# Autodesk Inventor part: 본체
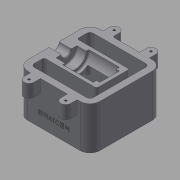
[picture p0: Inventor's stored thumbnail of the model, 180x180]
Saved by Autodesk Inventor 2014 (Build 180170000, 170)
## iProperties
Created: 2018-01
Part Number: 본체
Material: Generic
Document SubType Name: Modeling
Designer: user
Density: 1 g/cm^3
Appearance: Default
Author: user
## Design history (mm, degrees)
sketch "스케치2"
  geometry: L1 (-55, -55)-(55, -55); L2 (55, -55)-(55, 55); L3 (55, 55)-(-55, 55); L4 (-55, 55)-(-55, -55); L5 (-55, -55)-(55, 55); L6 (55, -55)-(-55, 55); 3 further points
  constraints: 12 end point, 3 midpoint, 2 parallel, 1 coincident, 1 horizontal, 1 perpendicular
  dimensions: "d2" = 110 distance of L2.end L3.end; "d3" = 110 distance of L1.end L2.end
extrude "돌출1" new body sketch "스케치2" stored distance "d4" = 65; taper "d5" = 0 deg
fillet "모깎기1" dims "d6" = 15
sketch "스케치3"
  geometry: L1 (40, 55)-(-40, 55) reference; L2 (-55, 40)-(-55, -40) reference; L3 (-40, -55)-(40, -55) reference; L4 (55, -40)-(55, 40) reference; L5 (-40, 45)-(40, 45); L6 (45, 40)-(45, -40); L7 (40, -45)-(-40, -45); L8 (-45, 25)-(-45, 40); L9 (0, 25)-(0, -25); L10 (-45, -25)-(-45, -40); L11 (-45, 25)-(32, 25); L12 (35, 22)-(35, -22); L13 (-45, -25)-(32, -25); A1 r 15 centre (40, 40) between (55, 40) and (40, 55) reference; A2 r 15 centre (-40, 40) between (-40, 55) and (-55, 40) reference; A3 r 15 centre (-40, -40) between (-55, -40) and (-40, -55) reference; A4 r 15 centre (40, -40) between (40, -55) and (55, -40) reference; A5 r 5 centre (40, 40) between (45, 40) and (40, 45); A6 r 5 centre (40, -40) between (40, -45) and (45, -40); A7 r 5 centre (-40, -40) between (-45, -40) and (-40, -45); A8 r 5 centre (-40, 40) between (-40, 45) and (-45, 40); A9 r 3 centre (32, 22) between (35, 22) and (32, 25); A10 r 3 centre (32, -22) between (32, -25) and (35, -22); 2 further points
  constraints: 18 end point, 12 point on circle, 6 centre point, 5 tangent, 3 perpendicular, 2 point on line, 1 coincident, 1 equal radius, 1 horizontal alignment, 1 midpoint, 1 parallel, 7 other
  dimensions: "d7" = 10 distance between parallel lines of L1 L5; "d8" = 50 distance of L9.start L9.end; "d66" = 20 distance between parallel lines of L12 L4; "d67" = 3 radius of A9
extrude "돌출2" cut sketch "스케치3" stored distance "d13" = 95.3375; taper "d14" = 0 deg
sketch "스케치4"
  geometry: L1 (-55, 32.5)-(-40, 32.5) reference; L2 (-55, 32.5)-(30, 32.5); L3 (30, 32.5)-(30, 46.5); L4 (29, 47.5)-(25, 47.5); L5 (25, 47.5)-(25, 51.5); L6 (24, 52.5)-(-21, 52.5); L7 (-22, 51.5)-(-22, 48.5); L8 (-22, 48.5)-(-35, 48.5); L9 (-36, 47.5)-(-36, 40); L10 (-36, 40)-(-55, 40); L11 (-55, 40)-(-55, 32.5); A1 r 1 centre (-35, 47.5) between (-35, 48.5) and (-36, 47.5); A2 r 1 centre (-21, 51.5) between (-21, 52.5) and (-22, 51.5); A3 r 1 centre (24, 51.5) between (25, 51.5) and (24, 52.5); A4 r 1 centre (29, 46.5) between (30, 46.5) and (29, 47.5); 5 further points
  constraints: 20 end point, 8 point on circle, 8 point on line, 8 tangent, 7 parallel, 4 centre point, 3 equal radius, 2 perpendicular, 1 collinear
  dimensions: "d15" = 85 distance of L1.start L2.end; "d16" = 15 diameter of L10 L2; "d17" = 32 diameter of L8 L2; "d18" = 40 diameter of L6 L2; "d19" = 30 diameter of L4 L2; "d20" = 5 distance of point (30, 47.5) L4.end; "d21" = 47 distance of point (25, 52.5) point (-22, 52.5); "d22" = 14 distance of L7.end point (-36, 48.5); "d23" = 1 radius of A1
revolve "회전1" sketch "스케치4" stored, may be unused: angle "d24" = 90 deg
chamfer "모따기1" distance "d25" = 1; stored, may be unused: second distance "d26" = 2, angle "d27" = 45 deg
sketch "스케치5"
  geometry: L1 (40, 55)-(-40, 55) reference; L2 (-55, 40)-(-55, 8.5) reference; L3 (-20.5, 65)-(-20.5, 55); L4 (-35.5, 65)-(-35.5, 55); A1 r 7.5 centre (-28, 65) between (-20.5, 65) and (-35.5, 65); 1 further point
  constraints: 4 end point, 2 perpendicular, 2 point on circle, 2 point on line, 2 tangent, 1 centre point
  dimensions: "d28" = 15 diameter of A1; "d29" = 27 distance from line of A1.centre L2; "d30" = 10 distance from line of L1 A1.centre
extrude "돌출3" join sketch "스케치5" distance "d31" = 20; taper "d32" = 0 deg
fillet "모깎기2" dims "d33" = 3
hole "구멍1" diameter "d36" = 3.242; stored, may be unused: countersink angle "d40" = 90 deg, drill point angle "d42" = 118 deg; dims "d34" = 10, "d35" = 10, "d37" = 9, "d38" = 4, "d39" = 2, "d41" = 11
sketch "스케치6"
  geometry: L1 (0, 65)-(31.5, 65) reference; L2 (0, 0)-(0, 65) reference; L3 (80, 0)-(0, 0) reference; L4 (80, 65)-(80, 0) reference; L5 (48.5, 65)-(80, 65) reference; L6 (24.96, 11)-(54.96, 11); L7 (54.96, 11)-(54.96, 29) reference; L8 (54.96, 29)-(24.96, 29); L9 (24.96, 29)-(24.96, 11); L10 (24.96, 11)-(54.96, 29); L11 (54.96, 11)-(24.96, 29); A1 r 8.5 centre (40, 65) between (31.5, 65) and (48.5, 65) reference; 2 further points
  constraints: 12 end point, 2 midpoint, 2 parallel, 1 horizontal, 1 perpendicular, 1 vertical
  dimensions: "d46" = 30 distance of L7.end L8.end; "d47" = 18 distance of L6.end L7.end; "d48" = 20 distance from line of L3 point (39.96, 20)
sketch "스케치7"
  geometry: L1 (-17, 6.682)-(-55, -3.5); L2 (-55, -21.5)-(-55, -3.5) reference; L3 (-55, -21.5)-(20, -2.5); L4 (-17, 17.643)-(20, 17.643) reference; L5 (20, 17.643)-(20, -2.5); L6 (-17, 6.682)-(-17, 17.643); L7 (24, 12.5)-(-21, 12.5) reference; L8 (-55, -3.5)-(-55, -21.5); 5 further points
  constraints: 12 end point, 2 horizontal, 2 midpoint, 1 collinear, 1 parallel, 1 perpendicular, 1 point on line, 1 vertical alignment
  dimensions: "d51" = 75 deg angle of L2 L1; "d54" = 37 distance of L4.start L4.end; "d78" = 30 vertical distance of point (35, -32.5) L3.end
extrude "돌출4" cut sketch "스케치7" stored distance "d55" = 30; taper "d56" = 0 deg
fillet "모깎기3" dims "d57" = 3
sketch "스케치10"
  geometry: L1 (45, 32.5)-(45, -32.5) reference; L2 (35, 32.5)-(35, -32.5) reference; L3 (-45, 32.5)-(-45, -32.5) reference; L4 (45, -32.5)-(-45, -32.5); L5 (-42.776, -23.34)-(32.776, -3.096); L6 (-45, -26.238)-(-45, -32.5); L7 (35, -0.198)-(35, 32.5); L8 (45, 32.5)-(35, 32.5); L9 (45, 32.5)-(45, -32.5); A1 r 3 centre (-42, -26.238) between (-42.776, -23.34) and (-45, -26.238); A2 r 3 centre (32, -0.198) between (32.776, -3.096) and (35, -0.198); 3 further points
  constraints: 12 end point, 6 point on line, 4 point on circle, 4 tangent, 3 collinear, 2 centre point, 2 perpendicular, 1 equal radius
  dimensions: "d68" = 105 deg angle of L5 L3; "d69" = 30 distance from line of L4 point (35, -2.5); "d70" = 3 radius of A1
extrude "돌출6" cut sketch "스케치10" stored distance "d71" = 60; taper "d72" = 0 deg
fillet "모깎기4" dims "d73" = 3
sketch "스케치11"
  geometry: L1 (80, 0)-(0, 0) reference; L2 (-15, 65)-(-15, 0) reference; 2 further points
  constraints: 1 other
  dimensions: "d74" = 55 distance from line of L2 point (40, 20); "d75" = 20 distance from line of L1 point (40, 20)
extrude "돌출7" join sketch "스케치11" distance "d76" = 0.5; taper "d77" = 0 deg
node "솔리드1"
pattern_linear "직사각형 패턴1" dims "d45" = 56
mirror "대칭1"
